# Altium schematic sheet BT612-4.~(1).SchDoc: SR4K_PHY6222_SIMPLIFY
size A2; Revision: V1.2; SheetNumber: 2; SheetTotal: 5
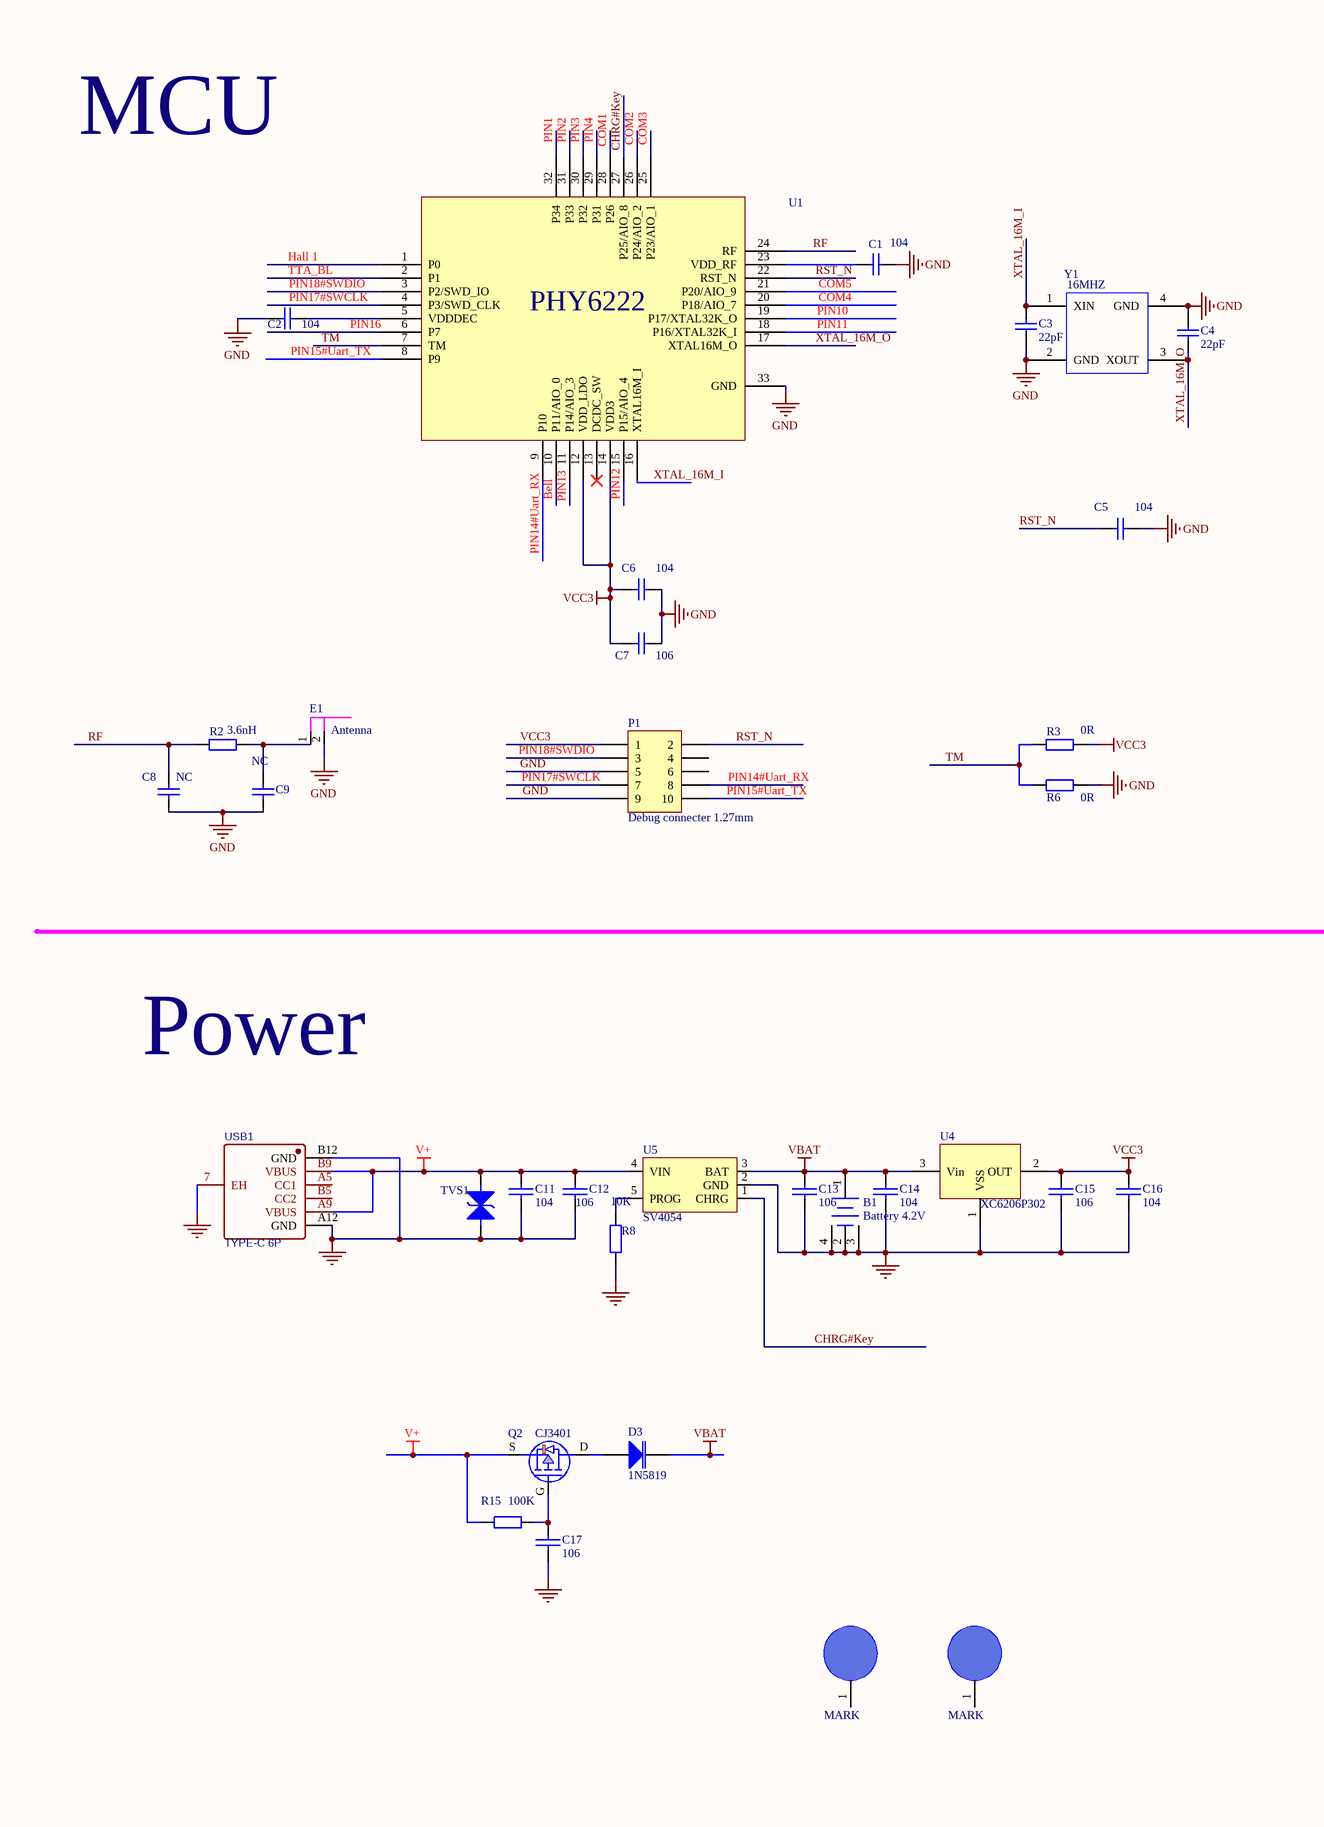
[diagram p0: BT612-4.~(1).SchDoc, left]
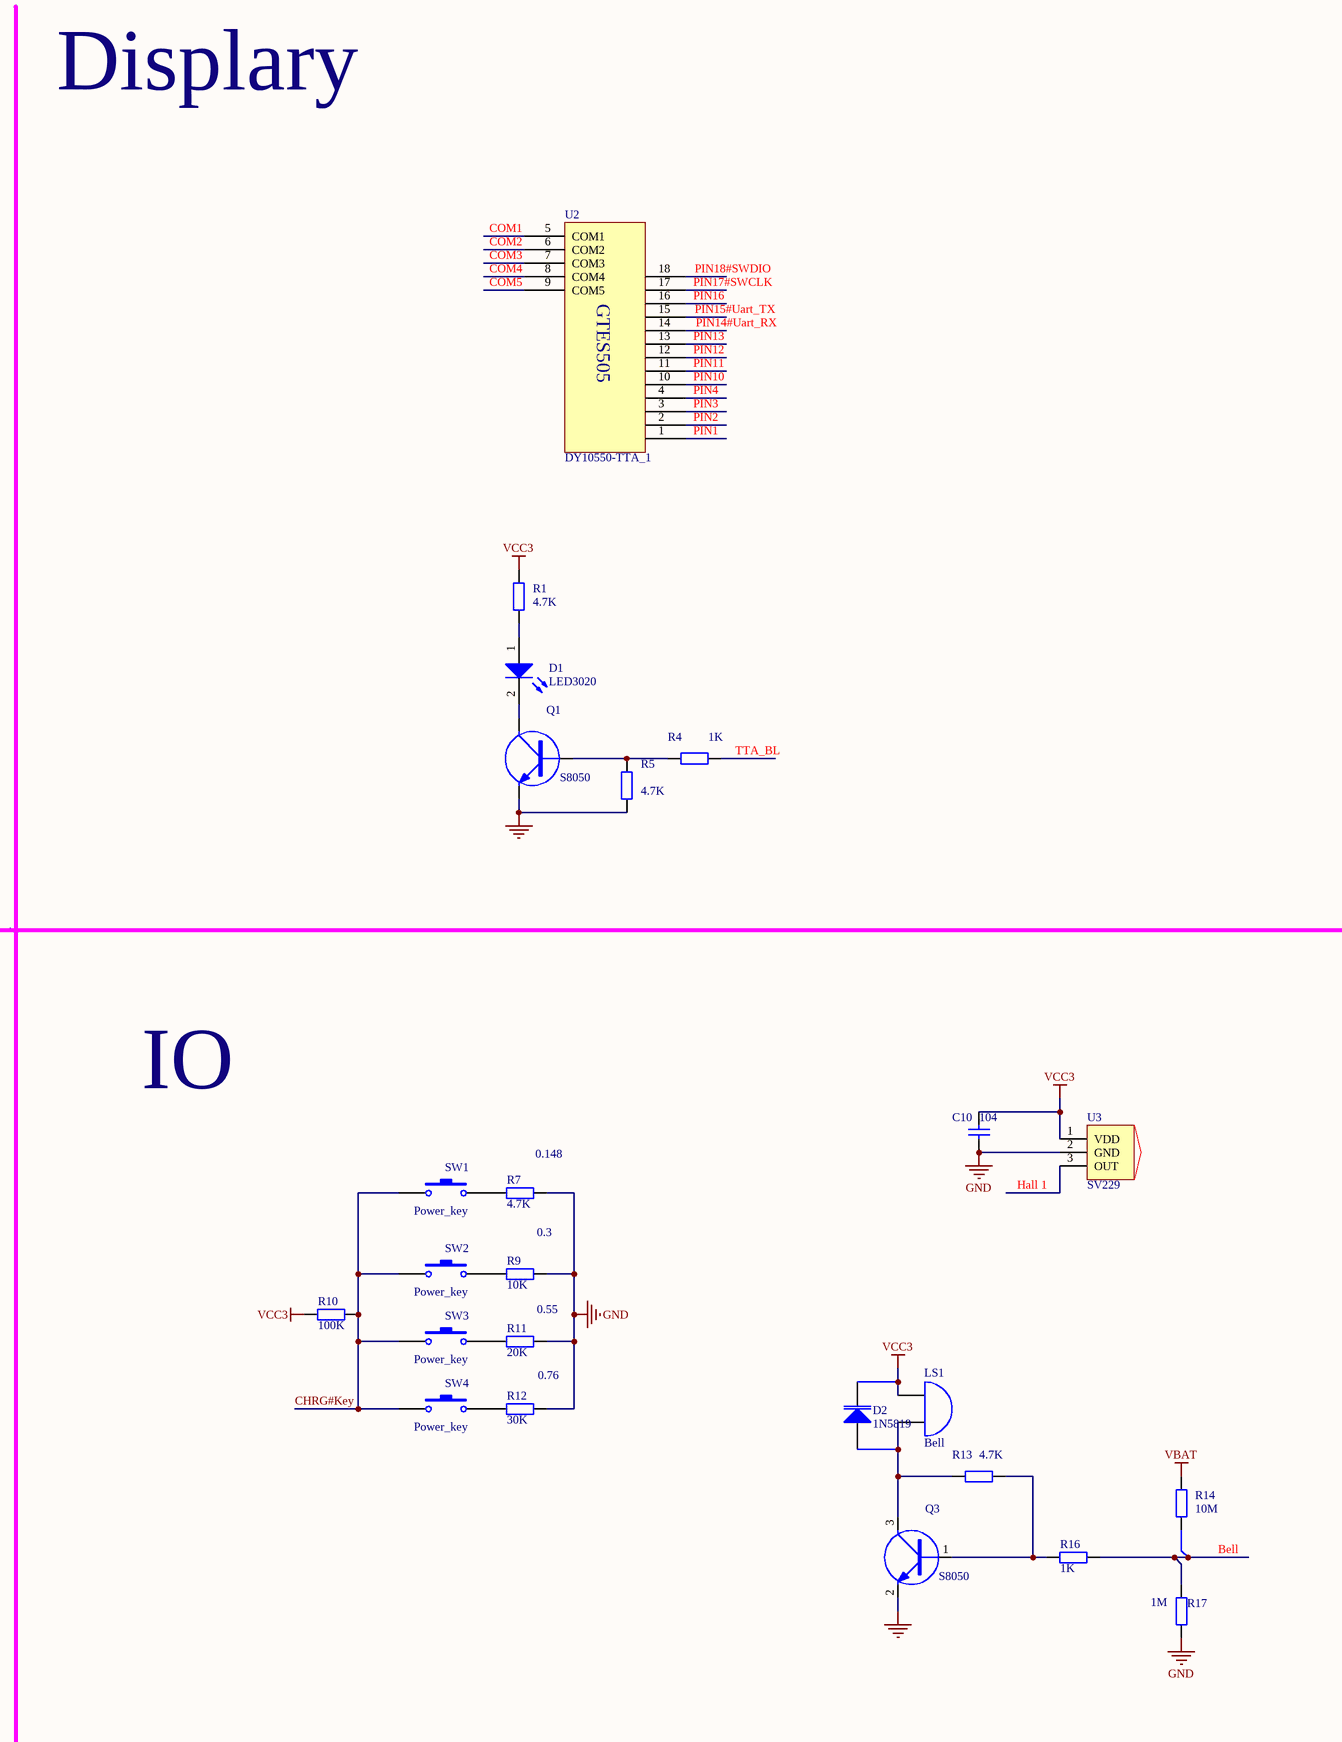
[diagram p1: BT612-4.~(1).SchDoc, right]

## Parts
B1  Battery 4.2V  [BAT2P-1.25]
C1  104  [0402C]
C2  104  [0402C]
C3  22pF  [0402C]
C4  22pF  [0402C]
C5  104  [0402C]
C6  104  [0402C]
C7  106  [0603-C]
C8  NC  [0402C]
C9  NC  [0402C]
C10  104  [0402C]
C11  104  [0402C]
C12  106  [0603-C]
C13  106  [0603-C]
C14  104  [0402C]
C15  106  [0603-C]
C16  104  [0402C]
C17  106  [0603-C]
D1  LED3020  [LED-3020]
D2  1N5819  [SOD323]
D3  1N5819  [SOD323]
E1  Antenna  [BT-ANT]
LS1  Bell  [BUZZ-12085]
P1  Debug connecter 1.27mm  [SIP5-X2-1.27]
Q1  S8050  [SOT23]
Q2  CJ3401  [SOT-23-GSD]
Q3  S8050  [SOT23]
R1  4.7K  [0402R]
R2  3.6nH  [0402R]
R3  0R  [0402R]
R4  1K  [0402R]
R5  4.7K  [0402R]
R6  0R  [0402R]
R7  4.7K  [0402R]
R8  10K  [0402R]
R9  10K  [0402R]
R10  100K  [0402R]
R11  20K  [0402R]
R12  30K  [0402R]
R13  4.7K  [0402R]
R14  10M  [0402R]
R15  100K  [0402R]
R16  1K  [0402R]
R17  1M  [0402R]
SW1  Power_key  [SW_PB_SMD_4X4]
SW2  Power_key  [SW_PB_SMD_4X4]
SW3  Power_key  [SW_PB_SMD_4X4]
SW4  Power_key  [SW_PB_SMD_4X4]
TP1  MARK  [MARK]
TP2  MARK  [MARK]
TVS1  TVS  [SOD323]  (value not drawn)
U1  PHY6222  [QFN32-4*4]  (value not drawn)
U2  DY10550-TTA_1  [GTES505液晶屏]
U3  SV229  [SOT23-3]
U4  XC6206P302  [SOT23]
U5  SV4054  [SOT23-5]
USB1  TYPE-C 6P  [TYPE-C 6P]
Y1  16MHZ  [JZ-3225]

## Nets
GND: B1.2(-) B1.3 B1.4 C1.2 C2.1 C3.2 C4.1 C5.2 C6.2 C7.2 C8.2 C9.2 C10.2 C11.1 C12.1 C13.1 C14.1 C15.1 C16.1 C17.1 E1.2 P1.5 P1.9 Q1.2(E) Q3.2(E) R5.1 R6.1 R7.2 R8.1 R9.2 R11.2 R12.2 R17.1 TVS1.1 U1.33(GND) U3.2(GND) U4.1(VSS) U5.2(GND) USB1.7(EH) USB1.A12(GND) USB1.B12(GND) Y1.2(GND) Y1.4(GND)
V+: C11.2 C12.2 Q2.S(SOURCE) R15.2 TVS1.2 U5.4(VIN) USB1.A9(VBUS) USB1.B9(VBUS)
VBAT: B1.1(+) C13.2 C14.2 D3.2 R14.2 U4.3(Vin) U5.3(BAT)
VCC3: C6.1 C7.1 C10.1 C15.2 C16.2 D2.2 LS1.1(A) P1.1 R1.2 R3.1 R10.1 U1.12(VDD_LDO) U1.14(VDD3) U3.1(VDD) U4.2(OUT)
Bell: R14.1 R16.2 R17.2 U1.10(P11/AIO_0)
CHRG#Key: R10.2 SW1.1 SW2.1 SW3.1 SW4.1 U1.27(P25/AIO_8) U5.1(CHRG)
COM1: U1.28(P26) U2.5(COM1)
COM2: U1.26(P24/AIO_2) U2.6(COM2)
COM3: U1.25(P23/AIO_1) U2.7(COM3)
COM4: U1.20(P18/AIO_7) U2.8(COM4)
COM5: U1.21(P20/AIO_9) U2.9(COM5)
Hall 1: U1.1(P0) U3.3(OUT)
PIN1: U1.32(P34) U2.1
PIN2: U1.31(P33) U2.2
PIN3: U1.30(P32) U2.3
PIN4: U1.29(P31) U2.4
PIN10: U1.19(P17/XTAL32K_O) U2.10
PIN11: U1.18(P16/XTAL32K_I) U2.11
PIN12: U1.15(P15/AIO_4) U2.12
PIN13: U1.11(P14/AIO_3) U2.13
PIN14#Uart_RX: P1.8 U1.9(P10) U2.14
PIN15#Uart_TX: P1.10 U1.8(P9) U2.15
PIN16: U1.6(P7) U2.16
PIN17#SWCLK: P1.7 U1.4(P3/SWD_CLK) U2.17
PIN18#SWDIO: P1.3 U1.3(P2/SWD_IO) U2.18
RF: C8.1 R2.2 U1.24(RF)
RST_N: C5.1 P1.2 U1.22(RST_N)
TM: R3.2 R6.2 U1.7(TM)
TTA_BL: R4.2 U1.2(P1)
XTAL_16M_I: C3.1 U1.16(XTAL16M_I) Y1.1(XIN)
XTAL_16M_O: C4.2 U1.17(XTAL16M_O) Y1.3(XOUT)
NetC1_1: C1.1 U1.23(VDD_RF)
NetC2_2: C2.2 U1.5(VDDDEC)
NetC9_1: C9.1 E1.1 R2.1
NetC17_2: C17.2 Q2.G(GATE) R15.1
NetD1_1: D1.1(A) R1.1
NetD1_2: D1.2(K) Q1.3(C)
NetD2_1: D2.1 LS1.2(B) Q3.3(C) R13.2
NetD3_1: D3.1 Q2.D(DRAIN)
NetQ1_1: Q1.1(B) R4.1 R5.2
NetQ3_1: Q3.1(B) R13.1 R16.1
NetR7_1: R7.1 SW1.2
NetR8_2: R8.2 U5.5(PROG)
NetR9_1: R9.1 SW2.2
NetR11_1: R11.1 SW3.2
NetR12_1: R12.1 SW4.2

Not connected (* = marked no-connect by the designer): P1 4 6; TP1 1; TP2 1; U1 13(DCDC_SW)*; USB1 A5(CC1) B5(CC2)

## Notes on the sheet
- MCU
- Displary
- Power
- IO
- (near R7) 0.148
- 0.3
- 0.55
- 0.76

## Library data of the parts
B1 = Battery: Multicell Battery
C1 = Cap: Capacitor; Value: 2.2uF
C2 = Cap: Capacitor; Value: 100pF
C3 C4 C8 C9 = Cap: Capacitor
C5 = Cap: Capacitor; Value: 1uF
C6 = Cap: Capacitor; Value: 0.1uF
C7 = Cap: Capacitor; Value: 10nF
C10 = Cap: Capacitor; Value: 100nF
C11-C17 = CAP: Capacitor
D1 = LED0: Typical INFRARED GaAs LED
D2 D3 = D Varactor: Variable Capacitance Diode; Note: Pin 2 is not connected and not drawn.
LS1 = Bell: Electrical Bell
P1 = Header 5X2: Header, 5-Pin, Dual row
Q1 Q3 = NPN: NPN Transistor
Q2 = P-MOS
R1 R4 R5 R9-R14 R16 R17 = Res2: Resistor
R2 R3 R6 = Res2: Resistor; Value: 0
R7 = Res2: Resistor; Value: 5K
R8 R15 = Res2: 1%@100mA
SW1-SW4 = SW-PB: Switch
TP1 TP2 = TP
U3 = 霍尔44E 938
USB1 = TYPE-C 6P: BOM_Manufacturer: SHOU HAN; Contributor: LCSC
Y1 = X1_1: PCB DECAL: 3225; Source_Path: E:\LI LELE\DESIGN KIT\DESIGN KIT_ESP8089_DEMO\ESP8089_DEMO.DSN; Value: 40MHz+/-10ppm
